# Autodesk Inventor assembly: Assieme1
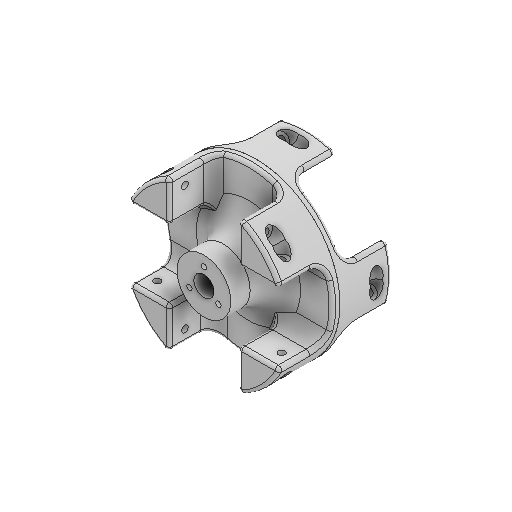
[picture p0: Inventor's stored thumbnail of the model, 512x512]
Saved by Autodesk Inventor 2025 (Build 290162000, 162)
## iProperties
Created: 2025-05
Part Number: Assieme1
Document SubType Name: Assembly
Designer: R5800u
Author: R5800u
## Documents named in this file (3)
- C:\Users\R5800u\Desktop\mecanum6\Assieme1.iam
- C:\Users\R5800u\Desktop\mecanum6\Parte1b.ipt
- C:\Users\R5800u\Desktop\mecanum5\Parte1c.ipt
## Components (2 placed, 2 different names)
1. Parte1b:1 — Rotazionale:1, Angolo:1
2. Parte1c:1 — Rotazionale:1, Angolo:1
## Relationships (2: RevoluteJoint 1, Angle 1)
- Rotazionale:1 [RevoluteJoint]: Parte1b:1 ↔ Parte1c:1
- Angolo:1 [Angle]: Parte1b:1 ↔ Parte1c:1
